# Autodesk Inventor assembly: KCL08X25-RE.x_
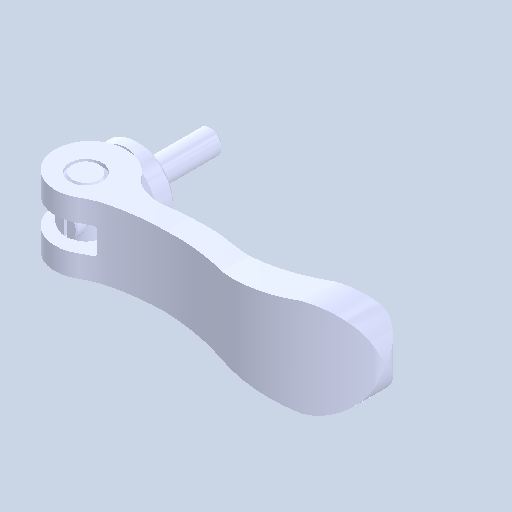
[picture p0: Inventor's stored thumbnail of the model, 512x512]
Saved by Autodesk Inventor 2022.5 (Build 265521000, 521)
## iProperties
Created: 2024-08
Part Number: KCL08X25-RE.x_
Document SubType Name: Assembly
Designer: ImaoCorp
Author: ImaoCorp
Sending System: SOLIDWORKS 2022-2022290
MC: AMD64
MC_MODEL: Intel64 Family 6 Model 60 Stepping 3, GenuineIntel
OS: Windows_NT
FRU: Parasolid Version 33.1, build 260,  4-25-2022
FORMAT: text
GUISE: transmit
KEY: FILEKCL08X25-RE.x_t
DATE: Thu Aug 29 10:50:20 2024
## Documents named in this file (5)
- Y:\5.更新分\2024年対応\1001_KCL\データ\kcl08x25-re\KCL08X25-RE.x_.iam
- Y:\5.更新分\2024年対応\1001_KCL\データ\kcl08x25-re\KCL08X25-RE_01.ipt
- Y:\5.更新分\2024年対応\1001_KCL\データ\kcl08x25-re\KCL08X25-RE_02.ipt
- Y:\5.更新分\2024年対応\1001_KCL\データ\kcl08x25-re\KCL08X25-RE_03.ipt
- Y:\5.更新分\2024年対応\1001_KCL\データ\kcl08x25-re\KCL08X25-RE_04.ipt
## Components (4 placed, 4 different names)
1. KCL08X25-RE_01
2. KCL08X25-RE_02
3. KCL08X25-RE_03
4. KCL08X25-RE_04
